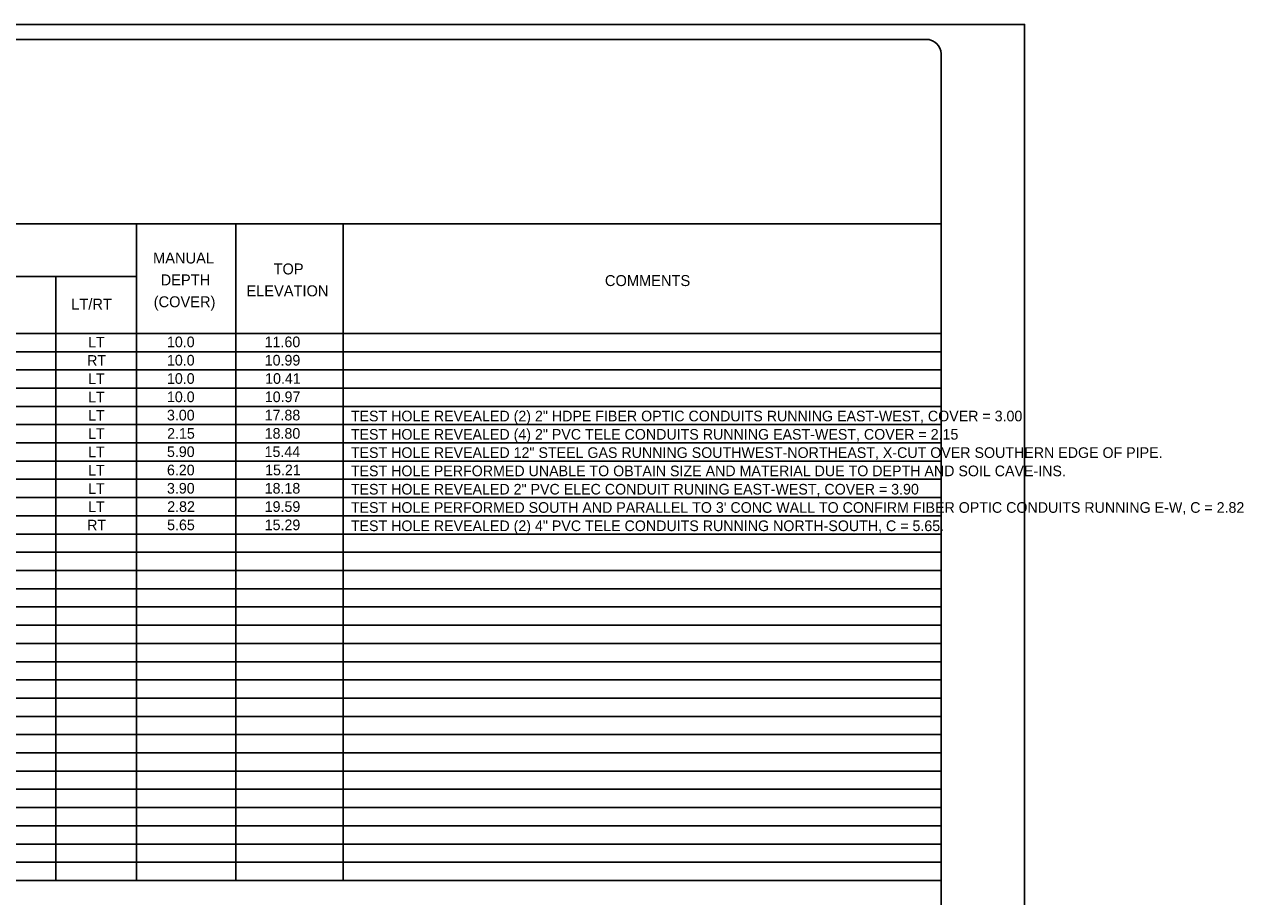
# Model space of a CAD drawing. Extents: x -769.4 to -731.2, y -2181.6 to -2171.
# Drawn here: x -739.22 to -731.19, y -2176.72 to -2170.98 of the extents above; entities that cross this region are included whole.
import ezdxf

# ---------------------------------------------------------------- set-up
doc = ezdxf.new("R2010")
doc.units = 0
for name, color, linetype in [('Default', 7, 'Continuous'), ('PlotBorder_dp', 7, 'Continuous'), ('TextSurveyLabel', 7, 'Continuous')]:
    doc.layers.add(name, color=color, linetype=linetype)

msp = doc.modelspace()

# ---------------------------------------------------------------- linework, layer by layer
at = {"layer": 'Default'}
for p, q in [((-733.2587, -2171.0816), (-748.4899, -2171.0816)), ((-733.1834, -2181.2948), (-733.1834, -2171.175))]:
    msp.add_line(p, q, dxfattribs=at)
msp.add_ellipse((-733.2769, -2171.1751), major_axis=(0, 0.0935), ratio=0.999927, start_param=4.712389, end_param=6.283185, dxfattribs=at)
at = {"layer": 'PlotBorder_dp'}
msp.add_lwpolyline([(-749.1334, -2181.5815), (-732.6334, -2181.5815), (-732.6334, -2170.9815), (-749.1334, -2170.9815)], close=True, dxfattribs=at)
at = {"layer": 'TextSurveyLabel'}
for p, q in [((-748.5834, -2172.2929), (-733.1834, -2172.2929)), ((-748.5434, -2172.2929), (-733.1834, -2172.2929)), ((-738.4807, -2172.2929), (-738.4807, -2176.6153)), ((-737.8265, -2172.2929), (-737.8265, -2176.6153)), ((-737.1201, -2172.294), (-737.1201, -2176.6153)), ((-741.0549, -2172.6404), (-738.4807, -2172.6404)), ((-739.0107, -2172.6404), (-739.0107, -2176.6153)), ((-748.5834, -2173.0153), (-733.1834, -2173.0153)), ((-748.5834, -2173.1354), (-733.1834, -2173.1354)), ((-748.5834, -2173.2553), (-733.1834, -2173.2553)), ((-748.5834, -2173.3752), (-733.1834, -2173.3752)), ((-748.5834, -2173.4953), (-733.1834, -2173.4953)), ((-748.5834, -2173.6154), (-733.1834, -2173.6154)), ((-748.5834, -2173.7353), (-733.1834, -2173.7353)), ((-748.5834, -2173.8552), (-733.1834, -2173.8552)), ((-748.5834, -2173.9753), (-733.1834, -2173.9753)), ((-748.5834, -2174.0954), (-733.1834, -2174.0954)), ((-748.5834, -2174.2153), (-733.1834, -2174.2153)), ((-748.5834, -2174.3352), (-733.1834, -2174.3352)), ((-748.5834, -2174.4553), (-733.1834, -2174.4553)), ((-748.5834, -2174.5754), (-733.1834, -2174.5754)), ((-748.5834, -2174.6953), (-733.1834, -2174.6953)), ((-748.5834, -2174.8154), (-733.1834, -2174.8154)), ((-748.5834, -2174.9353), (-733.1834, -2174.9353)), ((-748.5834, -2175.0552), (-733.1834, -2175.0552)), ((-748.5834, -2175.1753), (-733.1834, -2175.1753)), ((-748.5834, -2175.2954), (-733.1834, -2175.2954)), ((-748.5834, -2175.4153), (-733.1834, -2175.4153)), ((-748.5834, -2175.5352), (-733.1834, -2175.5352)), ((-748.5834, -2175.6553), (-733.1834, -2175.6553)), ((-748.5834, -2175.7754), (-733.1834, -2175.7754)), ((-748.5834, -2175.8953), (-733.1834, -2175.8953)), ((-748.5834, -2176.0152), (-733.1834, -2176.0152)), ((-748.5834, -2176.1353), (-733.1834, -2176.1353)), ((-748.5834, -2176.2554), (-733.1834, -2176.2554)), ((-748.5834, -2176.3753), (-733.1834, -2176.3753)), ((-748.5834, -2176.4954), (-733.1834, -2176.4954)), ((-748.5834, -2176.6153), (-733.1834, -2176.6153))]:
    msp.add_line(p, q, dxfattribs=at)

# ---------------------------------------------------------------- texts
for s, height, p in [('MANUAL ', 0.072, (-738.3712, -2172.5549)), ('DEPTH ', 0.072, (-738.3213, -2172.6989)), ('TOP', 0.072, (-737.5778, -2172.6269)), ('ELEVATION', 0.072, (-737.7568, -2172.7709)), ('COMMENTS', 0.072, (-735.3965, -2172.7034)), ('LT/RT', 0.072, (-738.9098, -2172.8584)), ('(COVER)', 0.072, (-738.3671, -2172.8429)), ('LT', 0.07, (-738.7985, -2173.1076)), ('10.0', 0.07, (-738.2797, -2173.1061)), ('11.60', 0.07, (-737.6364, -2173.106)), ('RT', 0.07, (-738.8052, -2173.228)), ('10.0', 0.07, (-738.2797, -2173.2265)), ('10.99', 0.07, (-737.6362, -2173.2264)), ('LT', 0.07, (-738.7985, -2173.3484)), ('10.0', 0.07, (-738.2797, -2173.3469)), ('10.41', 0.07, (-737.6335, -2173.3468)), ('LT', 0.07, (-738.7985, -2173.4688)), ('10.0', 0.07, (-738.2797, -2173.4673)), ('10.97', 0.07, (-737.6355, -2173.4672)), ('LT', 0.07, (-738.7985, -2173.5892)), ('3.00', 0.07, (-738.2797, -2173.5877)), ('17.88', 0.07, (-737.6363, -2173.5876)), ('TEST HOLE REVEALED (2) 2" HDPE FIBER OPTIC CONDUITS RUNNING EAST-WEST, COVER = 3.00', 0.07, (-737.0691, -2173.5937)), ('LT', 0.07, (-738.7985, -2173.7096)), ('2.15', 0.07, (-738.2786, -2173.7081)), ('18.80', 0.07, (-737.6364, -2173.708)), ('TEST HOLE REVEALED (4) 2" PVC TELE CONDUITS RUNNING EAST-WEST, COVER = 2.15', 0.07, (-737.0691, -2173.7141)), ('LT', 0.07, (-738.7985, -2173.83)), ('5.90', 0.07, (-738.2797, -2173.8285)), ('15.44', 0.07, (-737.6369, -2173.8284)), ('TEST HOLE REVEALED 12" STEEL GAS RUNNING SOUTHWEST-NORTHEAST, X-CUT OVER SOUTHERN EDGE OF PIPE. ', 0.07, (-737.0691, -2173.8345)), ('LT', 0.07, (-738.7985, -2173.9504)), ('6.20', 0.07, (-738.2797, -2173.9489)), ('15.21', 0.07, (-737.6335, -2173.9488)), ('TEST HOLE PERFORMED UNABLE TO OBTAIN SIZE AND MATERIAL DUE TO DEPTH AND SOIL CAVE-INS.', 0.07, (-737.0691, -2173.9549)), ('LT', 0.07, (-738.7985, -2174.0708)), ('3.90', 0.07, (-738.2797, -2174.0693)), ('18.18', 0.07, (-737.6363, -2174.0692)), ('TEST HOLE REVEALED 2" PVC ELEC CONDUIT RUNING EAST-WEST, COVER = 3.90', 0.07, (-737.0691, -2174.0753)), ('LT', 0.07, (-738.7985, -2174.1912)), ('2.82', 0.07, (-738.278, -2174.1897)), ('19.59', 0.07, (-737.6362, -2174.1896)), ("TEST HOLE PERFORMED SOUTH AND PARALLEL TO 3' CONC WALL TO CONFIRM FIBER OPTIC CONDUITS RUNNING E-W, C = 2.82 ", 0.07, (-737.0691, -2174.1957)), ('RT', 0.07, (-738.8052, -2174.3116)), ('5.65', 0.07, (-738.2786, -2174.3101)), ('15.29', 0.07, (-737.6362, -2174.31)), ('TEST HOLE REVEALED (2) 4" PVC TELE CONDUITS RUNNING NORTH-SOUTH, C = 5.65.', 0.07, (-737.0691, -2174.3161))]:
    msp.add_text(s, height=height, dxfattribs=at).set_placement(p)

doc.saveas('drawing.dxf')
